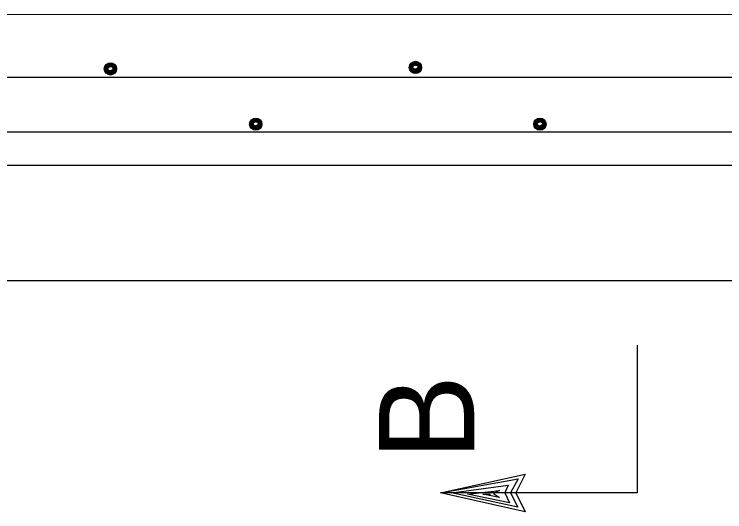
# Model space of a CAD drawing. Extents: x -0.08 to 2.83, y -0.03 to 1.92.
# Drawn here: x 0.8328 to 0.9299, y 1.4697 to 1.5377 of the extents above; entities that cross this region are included whole.
import ezdxf

# ---------------------------------------------------------------- set-up
doc = ezdxf.new("R2010")
doc.units = 0
for name, color, linetype in [('50', 7, 'Continuous'), ('51', 7, 'Continuous'), ('57', 7, 'Continuous')]:
    doc.layers.add(name, color=color, linetype=linetype)

msp = doc.modelspace()

# ---------------------------------------------------------------- linework, layer by layer
at = {"layer": '50'}
for p, q in [((0.723124, 1.537625), (1.051848, 1.537652)), ((0.723118, 1.517022), (1.051845, 1.517051)), ((0.728161, 1.501287), (1.051851, 1.50131))]:
    msp.add_line(p, q, dxfattribs=at)
at = {"layer": '51'}
for p, q in [((1.042478, 1.52901), (0.748338, 1.52901)), ((1.042478, 1.521539), (0.748338, 1.521539))]:
    msp.add_line(p, q, dxfattribs=at)
for points in [[(0.887668, 1.531188), (0.887993, 1.53108), (0.888223, 1.530857), (0.888364, 1.530565), (0.888367, 1.53028), (0.888298, 1.530056), (0.888154, 1.529879), (0.887951, 1.529728), (0.88775, 1.529653), (0.887481, 1.529633), (0.887225, 1.529696), (0.887042, 1.529823), (0.886894, 1.530043), (0.886812, 1.53028), (0.886812, 1.530581), (0.886933, 1.530824), (0.887078, 1.531005), (0.887235, 1.53111), (0.887442, 1.531165), (0.887619, 1.531162), (0.887809, 1.53109), (0.887996, 1.530998), (0.888164, 1.530857), (0.888252, 1.530713), (0.888308, 1.530575), (0.888325, 1.530437), (0.888325, 1.530253), (0.888252, 1.530099), (0.888154, 1.529971), (0.888052, 1.529863), (0.887901, 1.529761), (0.887724, 1.529709), (0.887531, 1.529696), (0.88737, 1.529719), (0.88718, 1.529778), (0.887081, 1.52985), (0.886989, 1.529981), (0.886907, 1.530102), (0.886868, 1.530253), (0.886848, 1.530427), (0.886897, 1.530647), (0.886996, 1.530824), (0.887117, 1.530962), (0.887327, 1.53108), (0.887527, 1.531116), (0.887724, 1.531064), (0.887911, 1.530988), (0.888078, 1.53086), (0.888187, 1.530742), (0.888246, 1.530598), (0.888279, 1.530404), (0.888236, 1.530227), (0.888161, 1.530099), (0.888033, 1.529955), (0.887855, 1.529833), (0.887675, 1.529781), (0.887475, 1.529768), (0.887314, 1.529791), (0.887117, 1.529892), (0.887006, 1.530043), (0.88695, 1.530191), (0.886914, 1.530407), (0.886963, 1.530631), (0.887042, 1.530798), (0.887157, 1.530909), (0.887301, 1.530998), (0.887442, 1.531037), (0.887613, 1.531037), (0.88775, 1.530988), (0.887885, 1.530916), (0.887993, 1.530837), (0.888131, 1.530713), (0.888203, 1.530565), (0.88821, 1.530404), (0.888174, 1.53026), (0.888036, 1.530066), (0.887885, 1.529955), (0.887695, 1.529863), (0.887485, 1.52985), (0.887344, 1.529886), (0.887235, 1.529912), (0.887081, 1.530027), (0.887035, 1.530145), (0.886966, 1.530339), (0.886999, 1.530549), (0.887088, 1.530736), (0.887193, 1.53087), (0.887353, 1.530959), (0.887504, 1.530991), (0.887678, 1.530952), (0.887862, 1.530857), (0.888016, 1.530749), (0.888131, 1.530647), (0.88817, 1.530476), (0.888154, 1.530407), (0.888131, 1.530293), (0.888059, 1.530201), (0.887924, 1.530063), (0.887842, 1.530007), (0.887741, 1.529955), (0.887652, 1.529919)], [(0.845992, 1.530975), (0.846313, 1.530867), (0.846553, 1.530644), (0.846691, 1.530352), (0.846691, 1.530066), (0.846622, 1.529843), (0.846477, 1.529666), (0.846274, 1.529515), (0.846074, 1.52944), (0.845802, 1.52942), (0.845549, 1.529482), (0.845365, 1.52961), (0.845214, 1.52983), (0.845132, 1.530066), (0.845132, 1.530368), (0.845254, 1.530611), (0.845401, 1.530791), (0.845565, 1.530896), (0.845762, 1.530952), (0.845949, 1.530949), (0.846136, 1.530877), (0.846323, 1.530785), (0.846487, 1.530644), (0.846576, 1.530499), (0.846641, 1.530362), (0.846648, 1.530224), (0.846648, 1.53004), (0.846576, 1.529886), (0.846477, 1.529758), (0.846376, 1.52965), (0.846222, 1.529548), (0.846048, 1.529495), (0.845854, 1.529482), (0.845697, 1.529505), (0.845506, 1.529564), (0.845405, 1.529636), (0.845313, 1.529768), (0.845231, 1.529889), (0.845191, 1.53004), (0.845172, 1.530214), (0.845221, 1.530434), (0.845319, 1.530611), (0.845441, 1.530749), (0.845661, 1.530867), (0.845848, 1.530903), (0.846048, 1.53085), (0.846238, 1.530775), (0.846399, 1.530647), (0.84651, 1.530529), (0.846569, 1.530385), (0.846602, 1.530191), (0.846559, 1.530014), (0.846484, 1.529886), (0.846353, 1.529741), (0.846179, 1.52962), (0.846002, 1.529568), (0.845798, 1.529554), (0.845638, 1.529577), (0.845441, 1.529679), (0.845329, 1.52983), (0.845277, 1.529978), (0.845241, 1.530194), (0.845287, 1.530417), (0.845365, 1.530585), (0.845483, 1.530696), (0.845624, 1.530785), (0.845762, 1.530824), (0.845936, 1.530824), (0.846074, 1.530775), (0.846208, 1.530703), (0.846313, 1.530624), (0.846458, 1.530499), (0.84653, 1.530352), (0.846537, 1.530191), (0.846504, 1.530047), (0.846363, 1.529853), (0.846208, 1.529741), (0.846018, 1.52965), (0.845811, 1.529636), (0.845667, 1.529673), (0.845565, 1.529699), (0.845405, 1.529814), (0.845362, 1.529932), (0.845296, 1.530125), (0.845329, 1.530335), (0.845418, 1.530522), (0.845519, 1.530657), (0.845674, 1.530745), (0.845834, 1.530778), (0.846008, 1.530739), (0.846195, 1.530644), (0.846343, 1.530535), (0.846458, 1.530434), (0.8465, 1.530263), (0.846477, 1.530194), (0.846458, 1.530079), (0.846382, 1.529988), (0.846248, 1.52985), (0.846166, 1.529794), (0.846067, 1.529741), (0.845972, 1.529705)], [(0.845972, 1.529705), (0.845726, 1.529751), (0.845565, 1.529768), (0.845483, 1.529853), (0.845401, 1.529978), (0.845365, 1.530125), (0.845365, 1.530289), (0.845431, 1.53044), (0.845519, 1.530565), (0.845631, 1.53065), (0.845752, 1.530709), (0.845953, 1.53069), (0.846123, 1.530611), (0.846248, 1.530522), (0.846389, 1.530424), (0.846441, 1.530283), (0.846376, 1.530125), (0.846323, 1.53006), (0.846238, 1.529955), (0.846149, 1.529886), (0.846048, 1.52983), (0.845953, 1.529804), (0.845848, 1.529794), (0.845762, 1.52981), (0.845615, 1.52985), (0.845542, 1.529883), (0.845506, 1.529922), (0.845451, 1.530014), (0.845431, 1.530073), (0.845421, 1.530148), (0.845421, 1.530243), (0.845431, 1.530299), (0.845451, 1.530385), (0.845506, 1.530457), (0.845697, 1.530601), (0.845798, 1.530644), (0.84593, 1.530637), (0.846038, 1.530591), (0.846113, 1.530555), (0.846215, 1.530486), (0.846274, 1.530434), (0.846343, 1.530352), (0.846372, 1.530273), (0.846323, 1.530142), (0.846297, 1.530099), (0.846238, 1.53004), (0.846166, 1.529978), (0.8461, 1.529932), (0.846035, 1.529906), (0.845979, 1.529869), (0.8459, 1.52985), (0.845864, 1.529843), (0.845788, 1.529869), (0.845743, 1.529886), (0.845674, 1.529906), (0.845611, 1.529945), (0.845549, 1.529991), (0.845516, 1.530047), (0.845496, 1.530142), (0.845496, 1.530214), (0.845496, 1.530289), (0.845529, 1.530352), (0.845585, 1.530434), (0.845651, 1.530486), (0.845716, 1.530522), (0.845788, 1.530555), (0.845848, 1.530572), (0.84592, 1.530529), (0.845992, 1.530506), (0.84609, 1.530463), (0.846162, 1.530424), (0.846215, 1.530378), (0.846248, 1.530306), (0.846245, 1.530214), (0.846208, 1.530125), (0.846179, 1.530089), (0.8461, 1.530027), (0.846038, 1.529991), (0.846008, 1.529971), (0.845953, 1.529955), (0.84589, 1.529935), (0.845825, 1.529932), (0.845775, 1.529935), (0.845746, 1.529945), (0.845697, 1.529988), (0.845667, 1.530017), (0.845638, 1.53004), (0.845611, 1.530056), (0.845585, 1.530079), (0.845569, 1.530125), (0.845569, 1.530175), (0.845585, 1.530243), (0.845588, 1.530296), (0.845611, 1.530352), (0.845638, 1.530398), (0.845674, 1.53044), (0.845716, 1.530463), (0.845775, 1.530473), (0.845841, 1.530486), (0.845887, 1.530499), (0.845936, 1.530473)], [(0.887652, 1.529919), (0.887403, 1.529965), (0.887235, 1.529981), (0.887157, 1.530066), (0.887078, 1.530191), (0.887042, 1.530339), (0.887042, 1.530503), (0.887104, 1.530654), (0.887193, 1.530778), (0.887307, 1.530864), (0.887429, 1.530923), (0.887626, 1.530903), (0.887796, 1.530824), (0.887924, 1.530736), (0.888065, 1.530637), (0.888121, 1.530496), (0.888052, 1.530339), (0.887996, 1.530273), (0.887911, 1.530168), (0.887819, 1.530099), (0.887724, 1.530043), (0.887626, 1.530017), (0.887527, 1.530007), (0.887442, 1.530024), (0.887291, 1.530063), (0.887219, 1.530096), (0.887183, 1.530135), (0.887124, 1.530227), (0.887104, 1.530286), (0.887098, 1.530362), (0.887098, 1.530457), (0.887104, 1.530512), (0.887124, 1.530598), (0.887183, 1.53067), (0.88737, 1.530814), (0.887475, 1.530857), (0.887603, 1.53085), (0.887714, 1.530804), (0.88779, 1.530768), (0.887888, 1.530699), (0.887951, 1.530647), (0.888016, 1.530565), (0.888042, 1.530486), (0.887996, 1.530355), (0.88797, 1.530312), (0.887911, 1.530253), (0.887842, 1.530191), (0.887773, 1.530145), (0.887708, 1.530119), (0.887655, 1.530083), (0.887577, 1.530063), (0.887537, 1.530056), (0.887462, 1.530083), (0.887409, 1.530099), (0.887353, 1.530119), (0.887288, 1.530158), (0.887225, 1.530204), (0.887189, 1.53026), (0.88717, 1.530355), (0.88717, 1.530427), (0.88717, 1.530503), (0.887206, 1.530565), (0.887262, 1.530647), (0.887324, 1.530699), (0.887393, 1.530736), (0.887462, 1.530768), (0.887527, 1.530785), (0.887593, 1.530742), (0.887668, 1.530719), (0.887767, 1.530677), (0.887836, 1.530637), (0.887888, 1.530591), (0.887924, 1.530519), (0.887911, 1.530427), (0.887885, 1.530339), (0.887855, 1.530303), (0.887773, 1.53024), (0.887714, 1.530204), (0.887678, 1.530184), (0.887626, 1.530168), (0.88757, 1.530148), (0.887501, 1.530145), (0.887449, 1.530148), (0.887412, 1.530158), (0.88737, 1.530201), (0.887344, 1.53023), (0.887314, 1.530253), (0.887288, 1.53027), (0.887262, 1.530293), (0.887239, 1.530339), (0.887239, 1.530388), (0.887262, 1.530457), (0.887265, 1.530509), (0.887288, 1.530565), (0.887314, 1.530611), (0.887353, 1.530654), (0.887393, 1.530677), (0.887449, 1.530686), (0.887517, 1.530699), (0.887563, 1.530713), (0.887613, 1.530686)], [(0.865848, 1.523432), (0.866169, 1.523321), (0.866409, 1.523094), (0.866546, 1.522809), (0.866546, 1.522524), (0.866477, 1.522304), (0.866333, 1.52212), (0.86613, 1.521976), (0.86593, 1.5219), (0.865657, 1.521881), (0.865405, 1.52194), (0.865221, 1.522064), (0.86507, 1.522284), (0.864988, 1.522524), (0.864988, 1.522822), (0.865109, 1.523065), (0.865257, 1.523249), (0.865421, 1.523354), (0.865618, 1.523409), (0.865805, 1.523406), (0.865992, 1.523334), (0.866179, 1.523242), (0.866343, 1.523094), (0.866432, 1.522957), (0.866497, 1.522819), (0.866504, 1.522684), (0.866504, 1.522497), (0.866432, 1.522346), (0.866333, 1.522215), (0.866231, 1.52211), (0.866077, 1.522009), (0.865903, 1.521956), (0.86571, 1.52194), (0.865552, 1.521959), (0.865362, 1.522022), (0.86526, 1.522094), (0.865168, 1.522228), (0.865086, 1.52235), (0.865047, 1.522497), (0.865027, 1.522675), (0.865077, 1.522888), (0.865175, 1.523065), (0.865296, 1.523213), (0.865516, 1.523321), (0.865703, 1.523357), (0.865903, 1.523311), (0.866094, 1.523232), (0.866254, 1.523104), (0.866366, 1.522986), (0.866425, 1.522842), (0.866458, 1.522645), (0.866415, 1.522471), (0.86634, 1.522346), (0.866208, 1.522196), (0.866035, 1.522074), (0.865857, 1.522028), (0.865654, 1.522009), (0.865493, 1.522035), (0.865296, 1.522143), (0.865185, 1.522284), (0.865132, 1.522435), (0.865096, 1.522648), (0.865142, 1.522875), (0.865221, 1.523045), (0.865339, 1.523154), (0.86548, 1.523242), (0.865618, 1.523285), (0.865792, 1.523285), (0.86593, 1.523232), (0.866064, 1.52316), (0.866169, 1.523085), (0.866313, 1.522957), (0.866386, 1.522812), (0.866392, 1.522645), (0.866359, 1.522511), (0.866218, 1.522317), (0.866064, 1.522196), (0.865874, 1.52211), (0.865667, 1.522094), (0.865523, 1.522127), (0.865421, 1.522153), (0.86526, 1.522274), (0.865218, 1.522389), (0.865152, 1.522589), (0.865185, 1.522796), (0.865273, 1.522976), (0.865375, 1.523111), (0.865529, 1.523203), (0.86569, 1.523232), (0.865864, 1.523193), (0.866051, 1.523094), (0.866199, 1.522996), (0.866313, 1.522888), (0.866356, 1.522727), (0.866333, 1.522648), (0.866313, 1.522537), (0.866238, 1.522442), (0.866103, 1.522307), (0.866021, 1.522248), (0.865923, 1.522196), (0.865828, 1.522163)], [(0.904686, 1.523432), (0.905011, 1.523321), (0.905241, 1.523094), (0.905382, 1.522809), (0.905385, 1.522524), (0.905316, 1.522304), (0.905172, 1.52212), (0.904968, 1.521976), (0.904768, 1.5219), (0.904499, 1.521881), (0.904243, 1.52194), (0.904059, 1.522064), (0.903912, 1.522284), (0.90383, 1.522524), (0.90383, 1.522822), (0.903951, 1.523065), (0.904096, 1.523249), (0.904253, 1.523354), (0.90446, 1.523409), (0.904637, 1.523406), (0.904827, 1.523334), (0.905014, 1.523242), (0.905182, 1.523094), (0.90527, 1.522957), (0.905326, 1.522819), (0.905342, 1.522684), (0.905342, 1.522497), (0.90527, 1.522346), (0.905172, 1.522215), (0.90507, 1.52211), (0.904919, 1.522009), (0.904742, 1.521956), (0.904548, 1.52194), (0.904388, 1.521959), (0.904197, 1.522022), (0.904099, 1.522094), (0.904007, 1.522228), (0.903925, 1.52235), (0.903886, 1.522497), (0.903866, 1.522675), (0.903915, 1.522888), (0.904014, 1.523065), (0.904135, 1.523213), (0.904345, 1.523321), (0.904545, 1.523357), (0.904742, 1.523311), (0.904929, 1.523232), (0.905096, 1.523104), (0.905204, 1.522986), (0.905264, 1.522842), (0.905296, 1.522645), (0.905254, 1.522471), (0.905178, 1.522346), (0.90505, 1.522196), (0.904873, 1.522074), (0.904693, 1.522028), (0.904493, 1.522009), (0.904332, 1.522035), (0.904135, 1.522143), (0.904023, 1.522284), (0.903968, 1.522435), (0.903932, 1.522648), (0.903981, 1.522875), (0.904059, 1.523045), (0.904174, 1.523154), (0.904319, 1.523242), (0.90446, 1.523285), (0.90463, 1.523285), (0.904768, 1.523232), (0.904903, 1.52316), (0.905011, 1.523085), (0.905149, 1.522957), (0.905221, 1.522812), (0.905227, 1.522645), (0.905191, 1.522511), (0.905054, 1.522317), (0.904903, 1.522196), (0.904712, 1.52211), (0.904502, 1.522094), (0.904361, 1.522127), (0.904253, 1.522153), (0.904099, 1.522274), (0.904053, 1.522389), (0.903984, 1.522589), (0.904017, 1.522796), (0.904105, 1.522976), (0.90421, 1.523111), (0.904371, 1.523203), (0.904522, 1.523232), (0.904696, 1.523193), (0.90488, 1.523094), (0.905034, 1.522996), (0.905149, 1.522888), (0.905188, 1.522727), (0.905172, 1.522648), (0.905149, 1.522537), (0.905077, 1.522442), (0.904942, 1.522307), (0.90486, 1.522248), (0.904758, 1.522196), (0.90467, 1.522163)], [(0.865828, 1.522163), (0.865582, 1.522209), (0.865421, 1.522228), (0.865339, 1.522317), (0.865257, 1.522435), (0.865221, 1.522589), (0.865221, 1.522743), (0.865287, 1.522898), (0.865375, 1.523019), (0.865487, 1.523104), (0.865608, 1.52317), (0.865808, 1.523144), (0.865979, 1.523065), (0.866103, 1.522976), (0.866245, 1.522881), (0.866297, 1.522737), (0.866231, 1.522589), (0.866179, 1.522517), (0.866094, 1.522409), (0.866005, 1.522346), (0.865903, 1.522284), (0.865808, 1.522261), (0.865703, 1.522248), (0.865618, 1.522271), (0.86547, 1.522307), (0.865398, 1.522337), (0.865362, 1.522376), (0.865306, 1.522471), (0.865287, 1.52253), (0.865277, 1.522606), (0.865277, 1.522698), (0.865287, 1.522763), (0.865306, 1.522842), (0.865362, 1.522914), (0.865552, 1.523058), (0.865654, 1.523094), (0.865785, 1.523088), (0.865893, 1.523049), (0.865969, 1.523009), (0.866071, 1.522947), (0.86613, 1.522888), (0.866199, 1.522812), (0.866228, 1.52273), (0.866179, 1.522599), (0.866153, 1.52256), (0.866094, 1.522497), (0.866021, 1.522435), (0.865956, 1.522389), (0.86589, 1.522363), (0.865834, 1.522327), (0.865756, 1.522307), (0.86572, 1.522304), (0.865644, 1.522327), (0.865598, 1.522346), (0.865529, 1.522363), (0.865467, 1.522406), (0.865405, 1.522451), (0.865372, 1.522511), (0.865352, 1.522599), (0.865352, 1.522675), (0.865352, 1.522743), (0.865385, 1.522812), (0.865441, 1.522888), (0.865506, 1.522947), (0.865572, 1.522976), (0.865644, 1.523009), (0.865703, 1.523029), (0.865775, 1.522986), (0.865848, 1.52296), (0.865946, 1.522924), (0.866018, 1.522881), (0.866071, 1.522835), (0.866103, 1.52277), (0.8661, 1.522675), (0.866064, 1.522589), (0.866035, 1.522553), (0.865956, 1.522481), (0.865893, 1.522451), (0.865864, 1.522432), (0.865808, 1.522409), (0.865746, 1.522396), (0.86568, 1.522389), (0.865631, 1.522396), (0.865601, 1.522406), (0.865552, 1.522442), (0.865523, 1.522474), (0.865493, 1.522497), (0.865467, 1.522511), (0.865441, 1.522537), (0.865424, 1.522589), (0.865424, 1.522635), (0.865441, 1.522698), (0.865444, 1.522753), (0.865467, 1.522809), (0.865493, 1.522855), (0.865529, 1.522898), (0.865572, 1.522924), (0.865631, 1.522927), (0.865697, 1.522947), (0.865743, 1.522957), (0.865792, 1.522927)], [(0.90467, 1.522163), (0.90442, 1.522209), (0.904253, 1.522228), (0.904174, 1.522317), (0.904096, 1.522435), (0.904059, 1.522589), (0.904059, 1.522743), (0.904122, 1.522898), (0.90421, 1.523019), (0.904325, 1.523104), (0.904447, 1.52317), (0.904643, 1.523144), (0.904814, 1.523065), (0.904942, 1.522976), (0.905083, 1.522881), (0.905139, 1.522737), (0.90507, 1.522589), (0.905014, 1.522517), (0.904929, 1.522409), (0.904837, 1.522346), (0.904742, 1.522284), (0.904643, 1.522261), (0.904545, 1.522248), (0.90446, 1.522271), (0.904309, 1.522307), (0.904237, 1.522337), (0.904201, 1.522376), (0.904141, 1.522471), (0.904122, 1.52253), (0.904115, 1.522606), (0.904115, 1.522698), (0.904122, 1.522763), (0.904141, 1.522842), (0.904201, 1.522914), (0.904388, 1.523058), (0.904493, 1.523094), (0.90462, 1.523088), (0.904732, 1.523049), (0.904807, 1.523009), (0.904906, 1.522947), (0.904968, 1.522888), (0.905034, 1.522812), (0.90506, 1.52273), (0.905014, 1.522599), (0.904988, 1.52256), (0.904929, 1.522497), (0.90486, 1.522435), (0.904791, 1.522389), (0.904725, 1.522363), (0.904673, 1.522327), (0.904594, 1.522307), (0.904555, 1.522304), (0.904479, 1.522327), (0.904427, 1.522346), (0.904371, 1.522363), (0.904306, 1.522406), (0.904243, 1.522451), (0.904207, 1.522511), (0.904187, 1.522599), (0.904187, 1.522675), (0.904187, 1.522743), (0.904224, 1.522812), (0.904279, 1.522888), (0.904342, 1.522947), (0.904411, 1.522976), (0.904479, 1.523009), (0.904545, 1.523029), (0.904611, 1.522986), (0.904686, 1.52296), (0.904785, 1.522924), (0.904853, 1.522881), (0.904906, 1.522835), (0.904942, 1.52277), (0.904929, 1.522675), (0.904903, 1.522589), (0.904873, 1.522553), (0.904791, 1.522481), (0.904732, 1.522451), (0.904696, 1.522432), (0.904643, 1.522409), (0.904588, 1.522396), (0.904519, 1.522389), (0.904466, 1.522396), (0.90443, 1.522406), (0.904388, 1.522442), (0.904361, 1.522474), (0.904332, 1.522497), (0.904306, 1.522511), (0.904279, 1.522537), (0.904256, 1.522589), (0.904256, 1.522635), (0.904279, 1.522698), (0.904283, 1.522753), (0.904306, 1.522809), (0.904332, 1.522855), (0.904371, 1.522898), (0.904411, 1.522924), (0.904466, 1.522927), (0.904535, 1.522947), (0.904581, 1.522957), (0.90463, 1.522927)]]:
    msp.add_lwpolyline(points, dxfattribs=at)
for centre in [(0.887588, 1.530397), (0.845913, 1.530184), (0.865769, 1.522641), (0.904606, 1.522641)]:
    msp.add_circle(centre, 0.00084, dxfattribs=at)
at = {"layer": '57'}
for p, q in [((0.917881, 1.492466), (0.917874, 1.472305)), ((0.917881, 1.492466), (0.917874, 1.472305)), ((0.890994, 1.472305), (0.902602, 1.47488)), ((0.902602, 1.47488), (0.901316, 1.472305)), ((0.890994, 1.472305), (0.901644, 1.474241)), ((0.901644, 1.474241), (0.900587, 1.472305)), ((0.892526, 1.472305), (0.900269, 1.473352)), ((0.900269, 1.473352), (0.899784, 1.472305)), ((0.917874, 1.472305), (0.890994, 1.472305)), ((0.902602, 1.469723), (0.890994, 1.472305)), ((0.901559, 1.470373), (0.892526, 1.472305)), ((0.894698, 1.472144), (0.899055, 1.47262)), ((0.90043, 1.470927), (0.894698, 1.472144)), ((0.899055, 1.471652), (0.896798, 1.472144)), ((0.896798, 1.472144), (0.897851, 1.472144)), ((0.899055, 1.47262), (0.898251, 1.472226)), ((0.898251, 1.472226), (0.899055, 1.471652)), ((0.899784, 1.472305), (0.90043, 1.470927)), ((0.900587, 1.472305), (0.901559, 1.470373)), ((0.901316, 1.472305), (0.902602, 1.469723))]:
    msp.add_line(p, q, dxfattribs=at)

# ---------------------------------------------------------------- texts
msp.add_text('B', height=0.013021, rotation=90, dxfattribs=at).set_placement((0.895622, 1.476793))

doc.saveas('drawing.dxf')
